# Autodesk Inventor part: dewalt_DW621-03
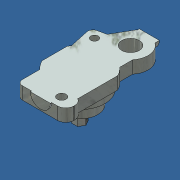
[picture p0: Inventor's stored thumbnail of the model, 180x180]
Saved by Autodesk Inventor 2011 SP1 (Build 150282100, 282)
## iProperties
Created: 2011-02
Part Number: dewalt_DW621-03
Material: 0.6025 GG-25 /  EN-GJL-250 / EN-JL1040
Catalog Web Link: www.mittelmeyer.de
Document SubType Name: Modellieren
Designer: TMT
Manufacturer: Standard
Standards Organization: Custom
Density: 1 g/cm^3
Author: TMT
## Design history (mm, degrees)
sketch "Skizze2"
  geometry: L1 (-40.5, 85)-(40.5, 85); L2 (40.5, 85)-(40.5, -85); L3 (40.5, -85)-(-40.5, -85); L4 (-40.5, -85)-(-40.5, 85); L5 (0, -119)-(0, 119) reference; L6 (-56.7, 0)-(56.7, 0) reference
  constraints: 8 end point, 2 parallel, 1 horizontal, 1 perpendicular, 2 other
  dimensions: "d4" = 170 distance of L3.end L1.start (= laenge_01); "d5" = 81 distance of L2.end L3.end (= breite_01)
extrude "Extrusion2" new body sketch "Skizze2" distance "d6" = 20 (= hoehe_01); taper "d7" = 0 deg
workplane "Arbeitsebene1"
sketch "Skizze3"
  geometry: L1 (-40.5, -85)-(-40.5, 85) reference; L2 (40.5, -85)-(-40.5, -85) reference; L3 (-30.223, -85)-(-30.223, -45.277); L4 (-30.223, -45.277)-(-40.5, -35); L5 (56.7, -15)-(-56.7, -15) reference; 1 further point
  constraints: 4 end point, 2 point on line, 1 perpendicular
  dimensions: "d8" = 10.27713 distance between parallel lines of L3 L1; "d9" = 45 deg angle of L4 L2; "d11" = 20 distance from line of L4.end L5
extrude "Extrusion3" cut sketch "Skizze3" stored distance "d12" = 42.5; taper "d13" = 0 deg
sketch "Skizze4"
  geometry: L1 (40.5, -85)-(47.5, -85); L2 (47.5, -85)-(47.5, -59); L3 (47.5, -59)-(40.5, -59); L4 (40.5, -59)-(40.5, -85); 1 further point
  constraints: 8 end point, 2 parallel, 1 horizontal, 1 perpendicular
  dimensions: "d14" = 7 distance of L1.start L1.end; "d15" = 26 distance of L1.end L2.end
extrude "Extrusion4" join sketch "Skizze4" stored distance "d16" = 10; taper "d17" = 0 deg
fillet "Rundung3" dims "d18" = 13
fillet "Rundung4" dims "d19" = 8
sketch "Skizze5"
  geometry: L1 (40.5, 85)-(40.5, -59) reference; L2 (-40.5, 85)-(40.5, 85) reference; L3 (-40.5, -35)-(-30.223, -45.277) reference; L4 (30.5, 85)-(30.5, 15); L5 (30.5, 15)-(40.5, 5); L6 (65.1, -15)-(-58.1, -15) reference; 1 further point
  constraints: 4 end point, 2 parallel, 2 point on line
  dimensions: "d20" = 45 deg angle of L5 L2 (derived); "d21" = 20 distance from line of L5.end L6; "d22" = 10 distance between parallel lines of L1 L4
extrude "Extrusion5" cut sketch "Skizze5" stored distance "d23" = 30.25; taper "d24" = 0 deg
sketch "Skizze6"
  geometry: L1 (-40.5, 85)-(30.5, 85) reference; L2 (65.1, -15)-(-58.1, -15) reference; L3 (0, -119)-(0, 119) reference; C1 r 28 at (9, 57); 1 further point
  constraints: 1 centre point, 1 tangent
  dimensions: "d25" = 72 distance from line of C1.centre L2; "d26" = 9 distance from line of L3 C1.centre
extrude "Extrusion6" join sketch "Skizze6" stored distance "d27" = 3.75; taper "d28" = 0 deg
sketch "Skizze7"
  geometry: L1 (-40.5, 85)-(30.5, 85) reference; L2 (-40.5, -35)-(-40.5, 85) reference; L3 (-30.223, -45.277)-(-30.223, -77) reference; L4 (40.5, 5)-(30.5, 15) reference; L5 (-40.5, 5)-(-30.223, 15.277); L6 (-30.223, 15.277)-(-30.223, 85); 1 further point
  constraints: 4 end point, 2 perpendicular, 2 point on line, 1 collinear
  dimensions: "d29" = 45 deg angle of L5 L1 (derived); "d30" = 40 distance of L5.start L2.start
extrude "Extrusion7" cut sketch "Skizze7" stored distance "d31" = 42.75; taper "d32" = 0 deg
sketch "Skizze8"
  geometry: L1 (-30.223, 15.277)-(-40.5, 5) reference; L2 (-40.5, -35)-(-40.5, 5) reference; L3 (30.5, 74.937)-(30.5, 85) reference; L4 (-30.223, 85)-(-30.223, 15.277) reference; L5 (-37.5, 8)-(-44.813, 41.204); L6 (-38.721, 50.738)-(-30.223, 52.609); L7 (-45, 42.925)-(-45, 106.002); L8 (37, 57)-(37, 122.341); A1 r 28 centre (9, 57) between (30.5, 39.063) and (30.5, 74.937) reference; A2 r 8 centre (-37, 42.925) between (-38.721, 50.738) and (-44.813, 41.204); 1 further point
  constraints: 8 end point, 4 point on circle, 4 tangent, 2 parallel, 2 point on line, 1 centre point, 1 perpendicular
  dimensions: "d34" = 8 radius of A2; "d35" = 82 distance between parallel lines of L8 L7; "d36" = 3 distance from line of L5.start L2; "d37" = 42 distance from line of L5.start L6
extrude "Extrusion8" join sketch "Skizze8" stored distance "d38" = 3.75; taper "d39" = 0 deg
sketch "Skizze9"
  geometry: L1 (30.5, 74.937)-(30.5, 85) reference; L2 (-30.223, 85)-(30.5, 85) reference; L3 (9, 85)-(30.5, 85); L4 (30.5, 85)-(30.5, 74.937); A1 r 28 centre (9, 57) between (30.5, 39.063) and (30.5, 74.937) reference; A2 r 28 centre (9, 57) between (30.5, 74.937) and (9, 85); 1 further point
  constraints: 4 end point, 2 collinear, 2 point on circle, 1 centre point, 1 coincident, 1 tangent
extrude "Extrusion9" cut sketch "Skizze9" stored distance "d40" = 31.25; taper "d41" = 0 deg
sketch "Skizze11"
  geometry: L1 (-39.223, 0)-(0, 0) reference; L2 (-16, 0)-(16, 0); A1 r 16 centre (0, 0) between (16, 0) and (-16, 0); 1 further point
  constraints: 2 end point, 2 point on circle, 2 point on line, 1 centre point, 1 coincident
  dimensions: "d42" = 32 diameter of A1
extrude "Extrusion10" join sketch "Skizze11" distance "d43" = 2; taper "d45" = 0 deg; dims "d44" = 8, "d46" = 0
sketch "Skizze12"
  geometry: L1 (0, 20)-(-56.723, 20) reference; A1 r 16 centre (-25.5, 20) between (-41.5, 20) and (-9.5, 20) reference; 1 further point
extrude "Extrusion11" join sketch "Skizze12" distance "d47" = 2; taper "d48" = 0 deg
sketch "Skizze13"
  geometry: L1 (-30.223, 85)-(-7, 85) reference; L2 (-30.223, 85)-(-30.223, 52.609) reference; L3 (-44.813, 41.204)-(-37.5, 8) reference; L4 (-30.223, 52.609)-(-25.042, 53.75); L5 (-7, 85)-(-25.042, 53.75); L6 (0, -121.8)-(0, 121.8) reference; 1 further point
  constraints: 4 end point, 1 perpendicular
  dimensions: "d49" = 30 deg angle of L6 L5
extrude "Extrusion12" cut sketch "Skizze13" stored distance "d50" = 54.75; taper "d51" = 0 deg
fillet "Rundung5" dims "d52" = 4
sketch "Skizze14"
  geometry: L1 (66, -15)-(-63.5, -15) reference; L2 (0, -121.8)-(0, 121.8) reference; C1 r 14 at (9, 57); C2 r 7 at (25, -69); A1 r 28 centre (9, 57) between (30.5, 39.063) and (25, 79.978) reference; 1 further point
  constraints: 2 centre point, 1 coincident
  dimensions: "d53" = 28 diameter of C1; "d54" = 54 distance from line of C2.centre L1; "d55" = 25 distance from line of L2 C2.centre; "d56" = 14 diameter of C2
extrude "Extrusion13" cut sketch "Skizze14" stored distance "d57" = 40.75; taper "d58" = 0 deg
sketch "Skizze16"
  geometry: L1 (-37.5, 8)-(-40.5, 5) reference; L2 (-40.5, -35)-(-40.5, 5) reference; L3 (40.5, 5)-(40.5, -59) reference; L4 (40.5, 5)-(30.5, 15) reference; L5 (66, -15)-(-63.5, -15) reference; L6 (40.5, -15)-(-40.5, -15); A1 r 45.169 centre (0, -15) between (-40.5, -35) and (40.5, -35); A2 r 45.169 centre (0, -15) between (40.5, 5) and (-40.5, 5); 1 further point
  constraints: 5 point on line, 4 end point, 4 point on circle, 2 centre point, 2 midpoint
extrude "Extrusion14" join sketch "Skizze16" stored distance "d60" = 2; taper "d61" = 0 deg
sketch "Skizze17"
  geometry: L1 (-25.042, 53.75)-(-38.721, 50.738) reference; L2 (-44.813, 41.204)-(-37.86, 9.635) reference; 2 further points
  dimensions: "d62" = 14 distance from line of L2 point (-29.85, 38.356); "d63" = 14 distance from line of point (-29.85, 38.356) L1
hole "Hole1" sketch "Skizze17" at (-29.85, 38.356) diameter "d64" = 12; stored, may be unused: countersink angle "d68" = 90 deg, drill point angle "d70" = 118 deg; dims "d65" = 6, "d66" = 4, "d67" = 2, "d69" = 8
sketch "Skizze18"
  geometry: L1 (0, -32.326)-(20, -32.326) reference; L2 (20, 0)-(0, 0) reference; L3 (10, 0)-(10, -32.326); L4 (20, 8)-(0, 8) reference; 2 further points
  constraints: 2 end point, 2 midpoint, 1 point on line
  dimensions: "d71" = 25 distance from line of point (10, -17) L4
hole "Hole2" sketch "Skizze18" at (10, -17) diameter "d72" = 12; stored, may be unused: countersink angle "d76" = 90 deg, drill point angle "d78" = 118 deg; dims "d73" = 6, "d74" = 4, "d75" = 2, "d77" = 8
sketch "Skizze19"
  geometry: L1 (0, 0)-(0, 20) reference; L2 (14.006, 0)-(14.006, 20) reference; L3 (14.006, 10)-(0, 10); L4 (-8, 0)-(-8, 20) reference; 2 further points
  constraints: 2 end point, 2 midpoint, 1 point on line
  dimensions: "d79" = 14 distance from line of point (6, 10) L4
hole "Hole3" sketch "Skizze19" at (6, 10) diameter "d80" = 4.917; stored, may be unused: countersink angle "d84" = 90 deg, drill point angle "d86" = 118 deg; dims "d81" = 6, "d82" = 4, "d83" = 2, "d85" = 8
sketch "Skizze20"
  geometry: C1 r 6 at (29.85, 38.356) reference; C2 r 9 at (29.85, 38.356); 1 further point
  constraints: 1 centre point, 1 coincident
  dimensions: "d87" = 18 diameter of C2
extrude "Extrusion15" join sketch "Skizze20" distance "d88" = 9; taper "d89" = 0 deg
sketch "Skizze21"
  geometry: C1 r 40 at (0, -15); A1 r 45.169 centre (0, -15) between (-30.5, 18.317) and (-40.5, 5) reference; 1 further point
  constraints: 1 centre point, 1 coincident
  dimensions: "d90" = 80 diameter of C1
extrude "Extrusion16" join sketch "Skizze21" distance "d91" = 9; taper "d92" = 0 deg
sketch "Skizze22"
  geometry: L1 (80.5, -9)-(0.5, -9) reference; L2 (80.5, 0)-(80.5, -9) reference; L3 (40.5, -9)-(40.5, 51.3); L4 (80.5, -9)-(69, -15); L5 (69, -15)-(69, -30); L6 (69, -30)-(40.5, -30); L7 (40.5, -30)-(40.5, -9); L8 (40.5, -9)-(80.5, -9); 1 further point
  constraints: 12 end point, 3 perpendicular, 2 parallel, 1 midpoint
  dimensions: "d93" = 57 diameter of L5 L3; "d94" = 21 distance between parallel lines of L6 L1; "d95" = 15 distance of L4.end L5.end
revolve "Umdrehung1" sketch "Skizze22" stored, may be unused: angle "d96" = 90 deg
sketch "Skizze23"
  geometry: C1 r 28.5 at (0, 0) reference; C2 r 7.5 at (0, 0); 1 further point
  constraints: 1 centre point, 1 coincident
  dimensions: "d97" = 15 diameter of C2
extrude "Extrusion17" join sketch "Skizze23" distance "d98" = 10; taper "d99" = 0 deg
sketch "Skizze24"
  geometry: L1 (63.5, 0)-(-66, 0) reference; L2 (-9.815, 0)-(-4.907, 8.5); L3 (-4.907, 8.5)-(4.907, 8.5); L4 (4.907, 8.5)-(9.815, 0); L5 (9.815, 0)-(4.907, -8.5); L6 (4.907, -8.5)-(-4.907, -8.5); L7 (-4.907, -8.5)-(-9.815, 0); C1 r 7.5 at (0, 0) reference; 2 further points
  constraints: 12 end point, 1 coincident, 1 point on line, 13 other
  dimensions: "d100" = 17 distance between parallel lines of L4 L7
extrude "Extrusion18" join sketch "Skizze24" distance "d101" = 14; taper "d102" = 0 deg
node "Volumenkörper1"
node "Volumenkörpern"
node "Oberflächenkörpern"
other parameters: "laenge_01" = 170 [user parameter; used in 1 equation term], "breite_01" = 81 [user parameter; used in 1 equation term], "hoehe_01" = 20 [user parameter; used in 1 equation term]
